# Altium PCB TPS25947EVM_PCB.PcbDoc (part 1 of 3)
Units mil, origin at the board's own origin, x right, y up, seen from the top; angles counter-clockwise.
Board outline 6500 x 3000 mil, 4 copper layers (L1-Top Layer, L2-GND1, L3-PWR/SIG, L4-Bottom Layer), stack 63.4 mil thick; 231 components, 92 nets, 448 pads, 577 vias.
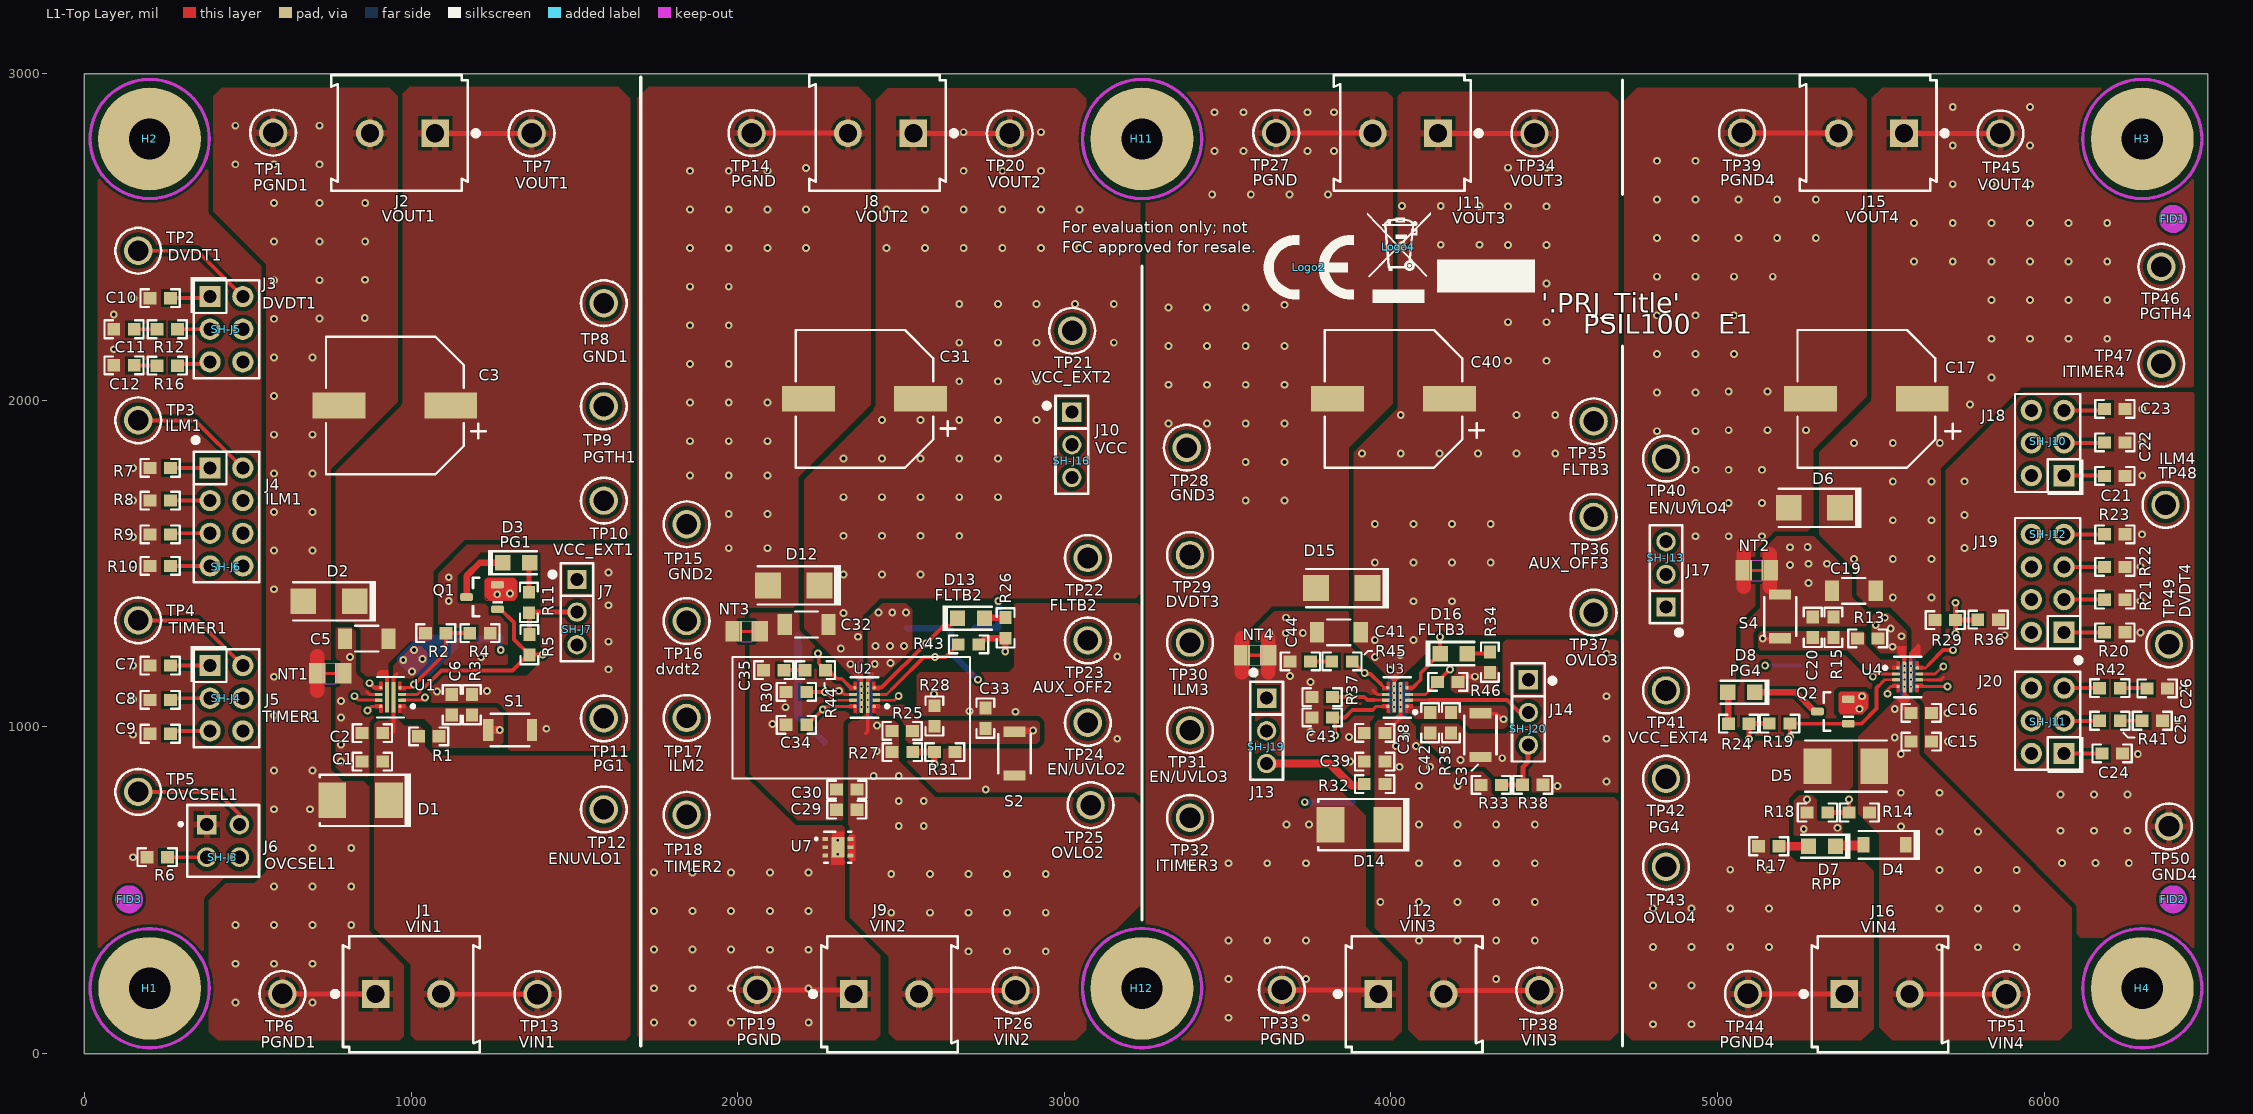
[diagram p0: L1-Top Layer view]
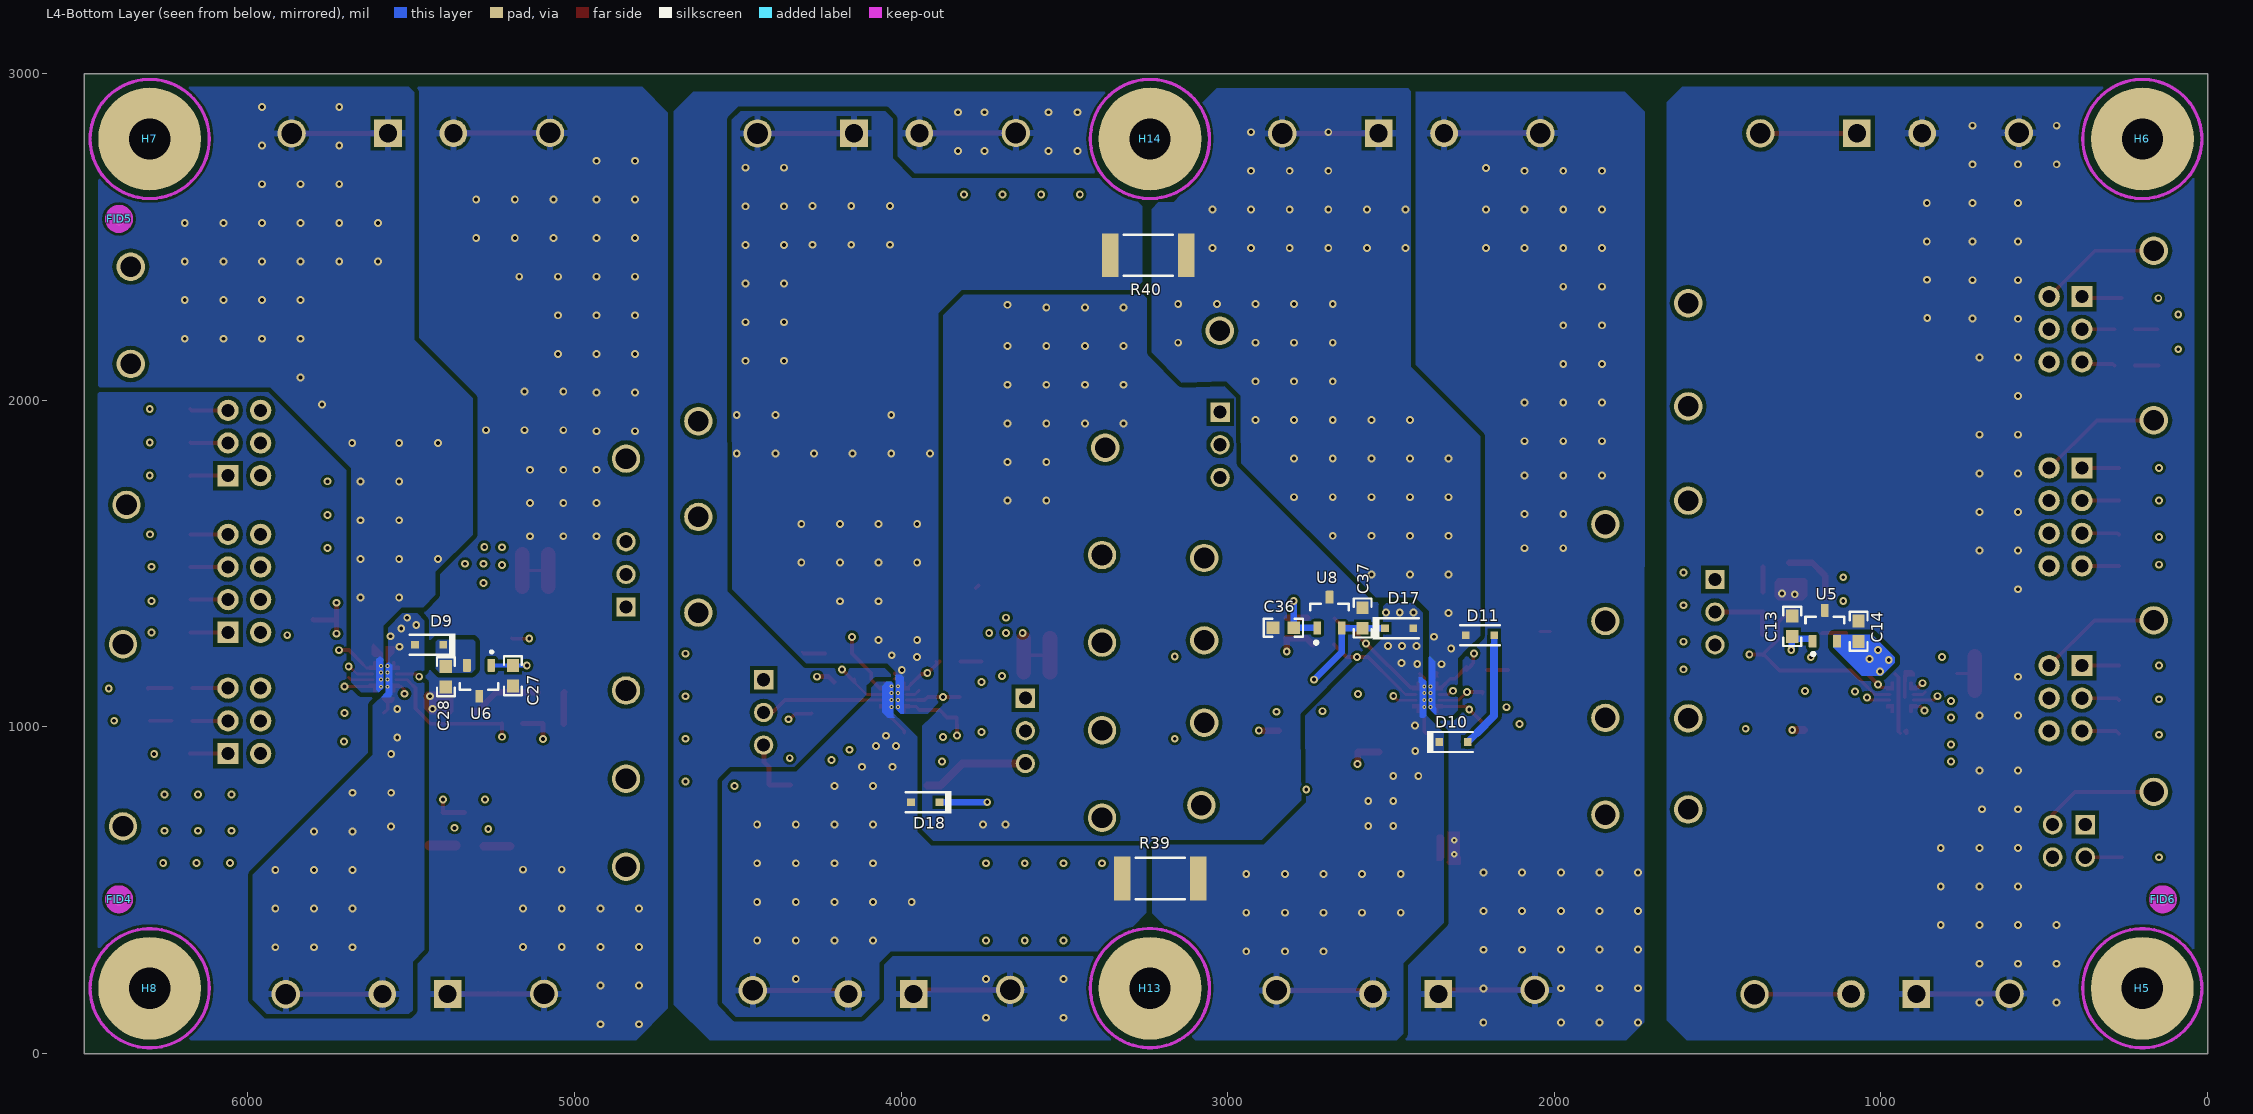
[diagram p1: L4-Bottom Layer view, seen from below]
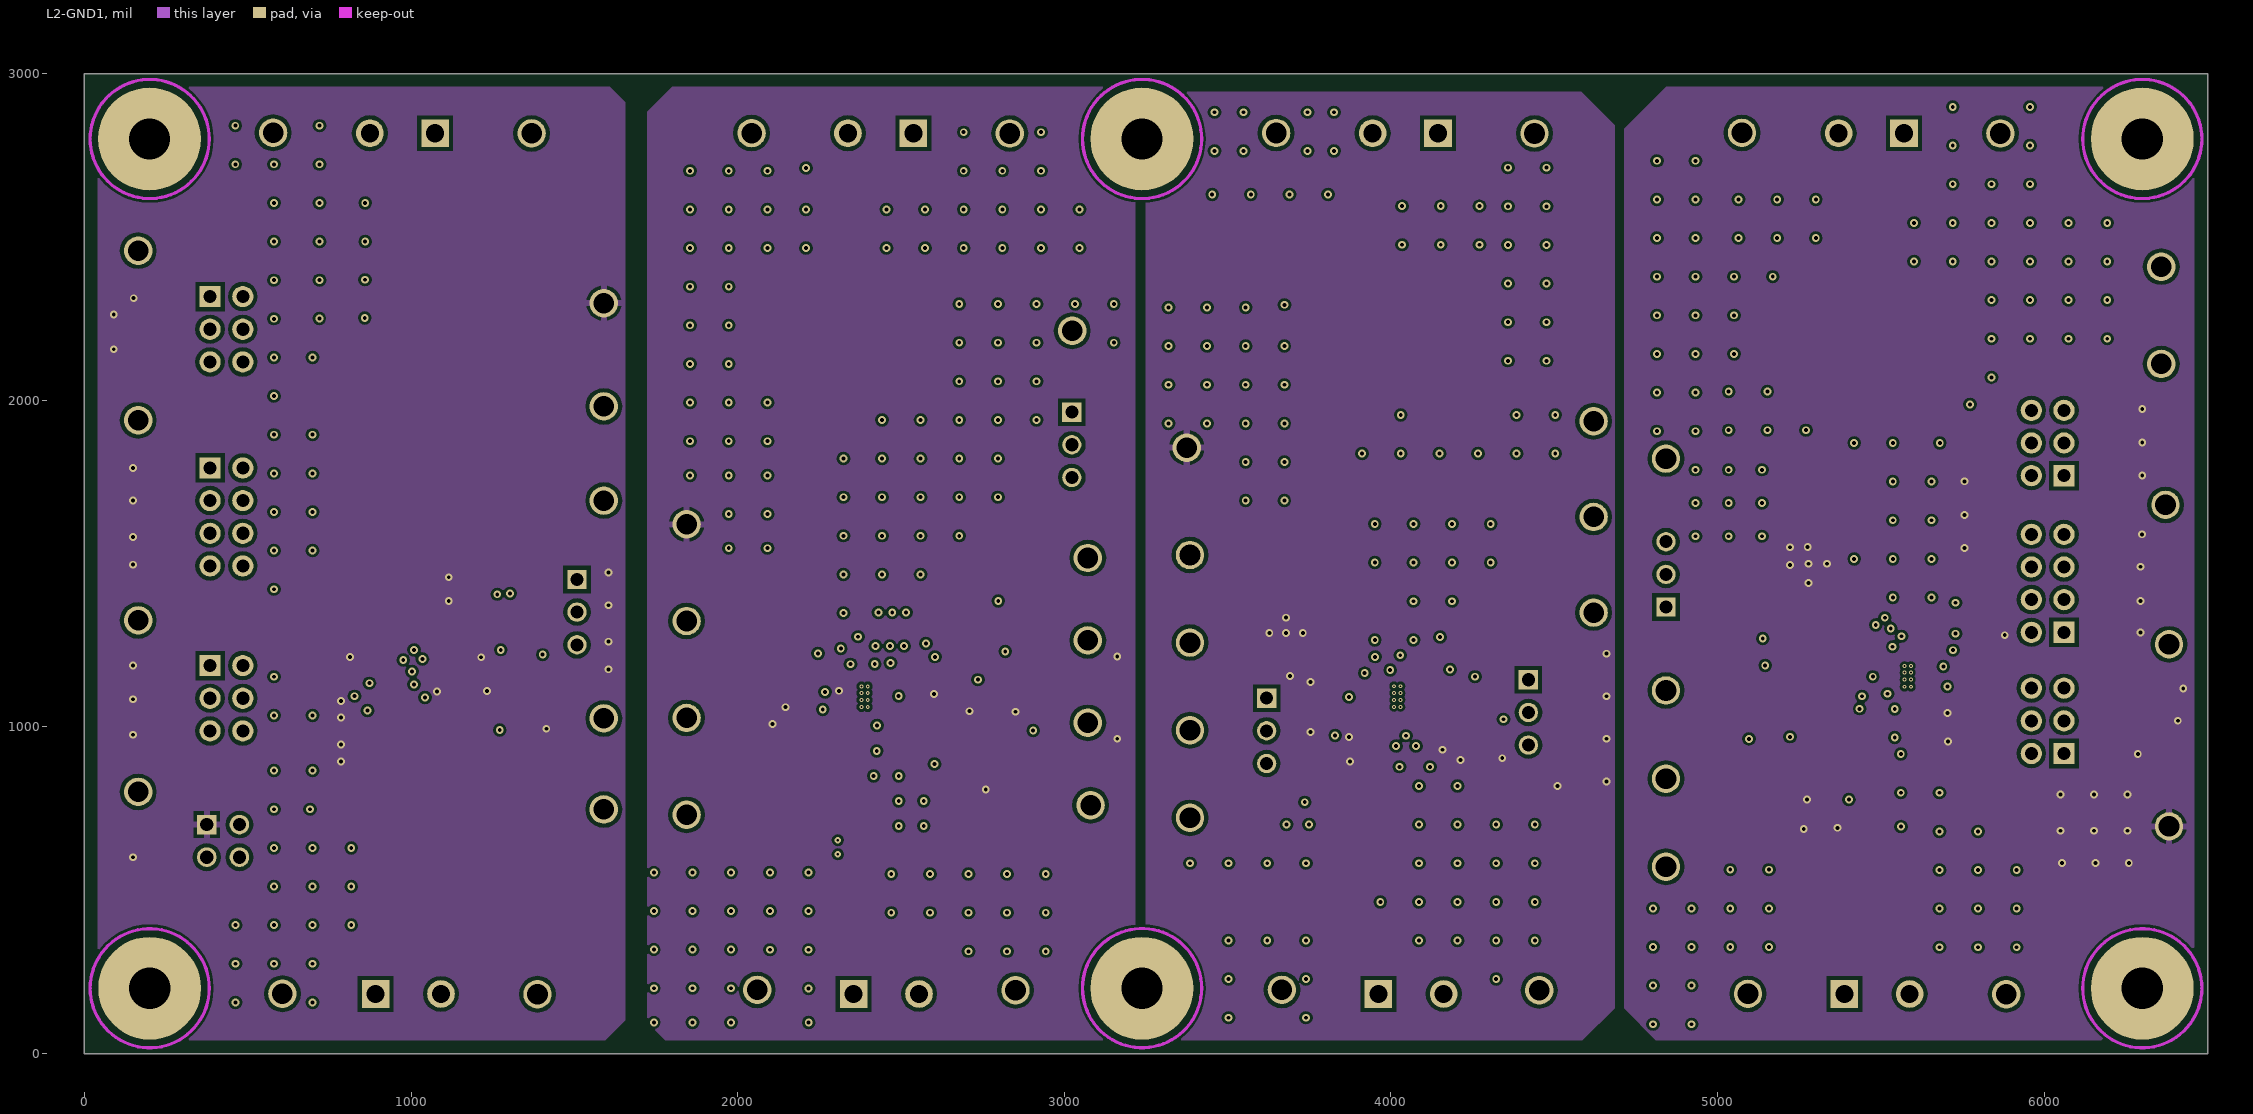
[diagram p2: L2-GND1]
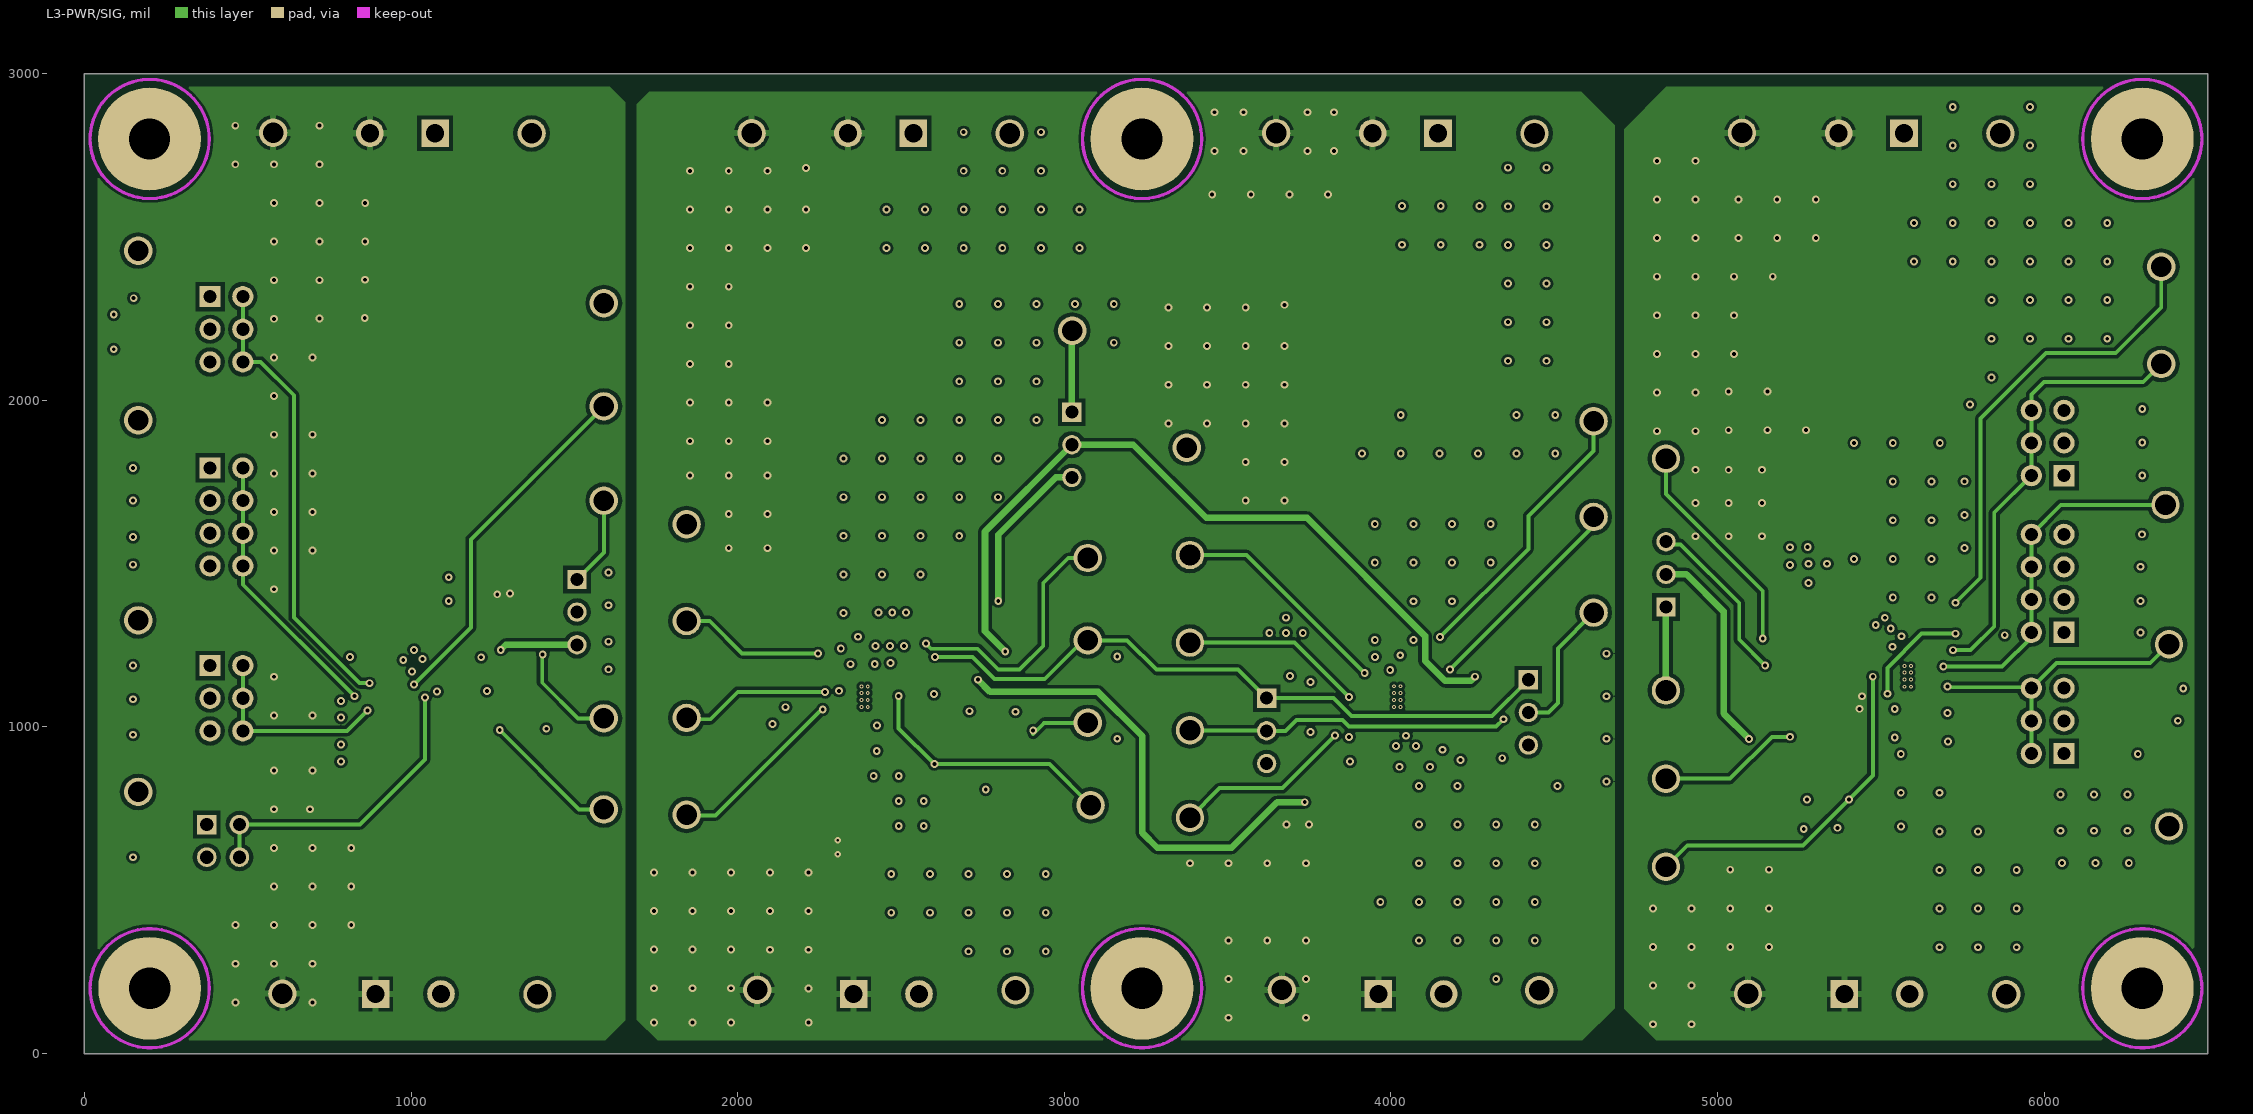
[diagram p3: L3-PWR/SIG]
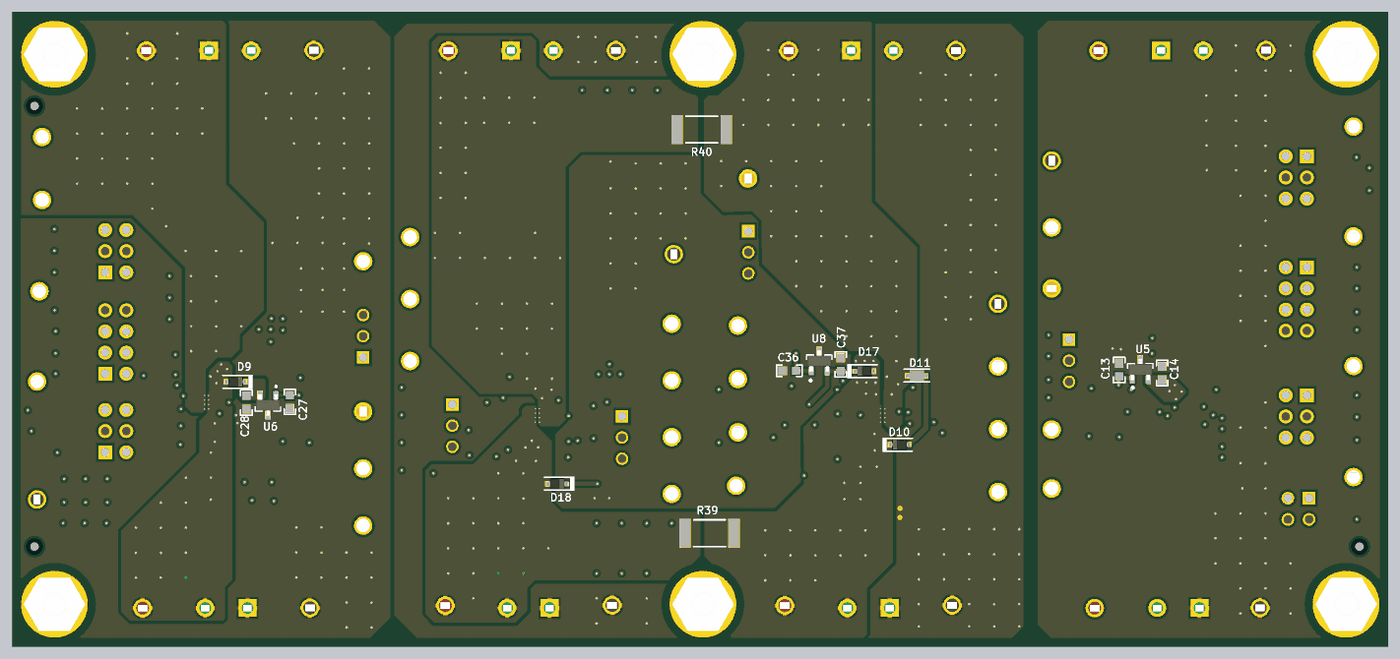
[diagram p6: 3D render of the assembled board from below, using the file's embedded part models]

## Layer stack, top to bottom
Top Solder: solder mask 0.4, Solder Resist, Dk 3.5
L1-Top Layer: signal copper 2.8
Dielectric 3: dielectric 10, FR-4 HIGH TG, Dk 4.2
L2-GND1: signal copper 1.4
Dielectric 2: dielectric 35, FR-4 HIGH TG, Dk 4.2
L3-PWR/SIG: signal copper 1.4
Dielectric1: core 10, FR-4 HIGH TG, Dk 4.2
L4-Bottom Layer: signal copper 2.8
Bottom Solder: solder mask 0.4, Solder Resist, Dk 3.5

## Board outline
0,0 6500,0 6500,3000 0,3000

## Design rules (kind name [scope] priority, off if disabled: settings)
AcuteAngle [All] p1: minimum=4.50000000000000E+0001 checktracksonly=FALSE
AssemblyTestPointUsage [All] p1: valid=2
BoardOutlineClearance [All] p1: gap=40 ignorepadtopadclearanceinfootprint=FALSE except(0: Track-OutlineEdge Text-OutlineEdge Text-CavityEdge Text-CutoutEdge Text-SplitBarrior Text-SplitContinuation)
Clearance Clearance_Fiducialmark [IsKeepOut and InComponentClass('FiducialMark') vs IsPad and InComponentClass('FiducialMark')] p1: gap=0 ignorepadtopadclearanceinfootprint=FALSE
Clearance Clearance_Keepouts [((IsTrack Or IsArc) And Not InPoly) And IsFree and IsKeepOut vs ((IsTrack Or IsArc) And Not InPoly) And IsFree and IsKeepOut] p2: gap=0 ignorepadtopadclearanceinfootprint=FALSE
Clearance "banana jack" [InPadClass('banan jack')] p3: gap=25 ignorepadtopadclearanceinfootprint=FALSE except(0: Arc-Hole Track-Hole SMDPad-Hole THPad-Hole Via-Hole Fill-Hole Poly-Hole Region-Hole Text-Hole)
Clearance [All] p4: gap=8 ignorepadtopadclearanceinfootprint=FALSE except(0: Arc-SMDPad Arc-Hole Track-Hole SMDPad-Hole THPad-Hole Via-Hole Fill-Hole Poly-Hole Region-Hole Text-Hole; 5.12: SMDPad-SMDPad; 5.8: Via-Via; 6.7: SMDPad-Via Via-Region; 6.8: Track-Via; 7.7: Track-SMDPad Track-Region; 7.87: SMDPad-Region; 10: Track-Poly THPad-THPad; 12: THPad-Poly Fill-Fill Fill-Poly; 15: Poly-Poly Poly-Region)
Clearance Clearance_Poly [InPolygon] p5: gap=15 ignorepadtopadclearanceinfootprint=FALSE except(0: Arc-SMDPad; 5.8: Via-Via; 6.7: SMDPad-Via Via-Region; 6.8: Track-Via; 10: SMDPad-Poly)
ComponentClearance ComponentClearance_MountingHoles_FiducialMarks [InComponentClass('Mounting Holes') vs InComponentClass('FiducialMark')] p1: gap=50 collisioncheckmode=3 verticalgap=10 showdistances=FALSE
ComponentClearance ComponentClearance_Shunt [InComponentClass('Header') vs InComponentClass('Shunt')] p2: gap=0 collisioncheckmode=3 verticalgap=0 showdistances=FALSE
ComponentClearance ComponentClearance_Logo [InComponentClass('Logo')] p3: gap=0 collisioncheckmode=3 verticalgap=0 showdistances=FALSE
ComponentClearance ComponentClearance_ScrewToNut [(HasFootprint('NY PMS 440 0025 PH')) vs (HasFootprint('Keystone_1902C'))] p4: gap=5 collisioncheckmode=3 verticalgap=10 showdistances=FALSE
ComponentClearance ComponentClearance_MountingHoles [InComponentClass('Mounting Holes')] p5: gap=100 collisioncheckmode=3 verticalgap=100000 showdistances=FALSE
ComponentClearance ComponentClearance_SmallPassives [HasFootprint('0201*') or HasFootprint('0402*') or HasFootprint('0508') or HasFootprint('0603*') or HasFootprint('0612') or HasFootprint('0805*') or HasFootprint('0815*') or HasFootprint('0830*') or HasFootprint('1206*') or HasFootprint('1210*') or HasFootprint('1808*') or HasFootprint('1812*') or HasFootprint('1825*') or HasFootprint('2010*') or HasFootprint('2220*') or HasFootprint('2225*') or HasFootprint('2512*') or HasFootprint('2728*') or HasFootprint('3518*') vs HasFootprint('0201*') or HasFootprint('0402*') or HasFootprint('0508') or HasFootprint('0603*') or HasFootprint('0612') or HasFootprint('0805*') or HasFootprint('0815*') or HasFootprint('0830*') or HasFootprint('1206*') or HasFootprint('1210*') or HasFootprint('1808*') or HasFootprint('1812*') or HasFootprint('1825*') or HasFootprint('2010*') or HasFootprint('2220*') or HasFootprint('2225*') or HasFootprint('2512*') or HasFootprint('2728*') or HasFootprint('3518*')] p6: gap=14.96 collisioncheckmode=3 verticalgap=10 showdistances=FALSE
ComponentClearance ComponentClearance_THtoSMT [IsThruComponent vs IsSMTComponent] p7: gap=40 collisioncheckmode=3 verticalgap=30 showdistances=FALSE
ComponentClearance ComponentClearance_THtoTH [IsThruComponent vs IsThruComponent] p8: gap=30 collisioncheckmode=3 verticalgap=30 showdistances=FALSE
ComponentClearance [All] p9: gap=10 collisioncheckmode=3 verticalgap=10 showdistances=FALSE
DiffPairsRouting [All] p1: maxlimit=100 minlimit=10 mostfreqgap=10 toplayer_minwidth=15 toplayer_maxwidth=15 toplayer_prefwidth=15 midlayer1_minwidth=15 midlayer1_maxwidth=15 midlayer1_prefwidth=15 midlayer2_minwidth=15 midlayer2_maxwidth=15 midlayer2_prefwidth=15 bottomlayer_minwidth=15 bottomlayer_maxwidth=15 bottomlayer_prefwidth=15 maxuncoupledlength=1000
FabricationTestPointUsage TestPointUsage [All] p1: valid=2 allowmultiple=FALSE
FabricationTestpoint Testpoint [All] p1: side=3 testpointundercomponent=TRUE minsize=40 maxsize=100 preferedsize=60 minholesize=0 maxholesize=40 preferedholesize=32 testpointgrid=1 allowsidetop=TRUE allowsidebottom=TRUE usegrid=TRUE gridtolerance=0.01
FanoutControl Fanout_LCC [IsLCC] p1: bgadir=Out bgaviamode=Centered fanoutstyle=Auto fanoutdirection=Alternating viagrid=1 // Fanout_LCC (Default Rule)
FanoutControl Fanout_BGA [IsBGA] p2: bgadir=Out bgaviamode=Centered fanoutstyle=Auto fanoutdirection=Alternating viagrid=1 // Fanout_BGA (Default Rule)
FanoutControl Fanout_Default [All] p4: bgadir=Out bgaviamode=Centered fanoutstyle=Auto fanoutdirection=Alternating viagrid=1 // Fanout_Default (Default Rule)
FanoutControl Fanout_Small [(CompPinCount < 5)] p5: bgadir=Out bgaviamode=Centered fanoutstyle=Auto fanoutdirection=OutThenIn viagrid=1 // Fanout_Small (Default Rule)
HoleSize [All] p1: absolutevalues=TRUE maxlimit=251 minlimit=6 maxpercent=80.000 minpercent=20.000
MinimumAnnularRing MinimumAnnularRing_ThermalPadVias [IsVia and InAnyComponent] p1: minimumring=5.91
MinimumAnnularRing [All] p2: minimumring=3
MinimumSolderMaskSliver MinimumSolderMaskSliver_Logo [InComponentClass('Logo') vs InComponentClass('Logo')] p1: minsoldermaskwidth=0.7
MinimumSolderMaskSliver [All] p2: minsoldermaskwidth=4
PlaneConnect [All] p1: planeconnectstyle=Relief reliefexpansion=10 reliefentries=4 reliefconductorwidth=10 reliefairgap=10
PolygonConnect [All] p1: thpad.connectstyle=Relief thpad.reliefconductorwidth=20 thpad.reliefentries=4 thpad.polygonreliefangle="90 Angle" thpad.airgapwidth=10 smdpad.connectstyle=Direct smdpad.reliefconductorwidth=10 smdpad.reliefentries=4 smdpad.polygonreliefangle="90 Angle" smdpad.airgapwidth=10 via.connectstyle=Direct via.reliefconductorwidth=10 via.reliefentries=4 via.polygonreliefangle="90 Angle" via.airgapwidth=10
RoutingVias ThermalPadVias [IsVia and InAnyComponent] p1: holewidth=7.87 width=19.68 viastyle="Through Hole" minholewidth=6 minwidth=12 maxholewidth=12.99 maxwidth=23.62
RoutingVias [All] p2: holewidth=12 width=24 viastyle="Through Hole" minholewidth=6 minwidth=12 maxholewidth=40 maxwidth=65
SilkToBoardRegionClearance [Not ((IsComment or IsDesignator) And (Hide <> 'False')) and not InRegion(1000,500,4000,800)] p1:
SilkToSilkClearance SilkToSilkClearance_Pb-FreeLogo [(HasFootprint('Pb-Free_Overlay_Medium') OR HasFootprint('Pb-Free_Overlay_Small')) vs (HasFootprint('Pb-Free_Overlay_Medium') OR HasFootprint('Pb-Free_Overlay_Small'))] p1: silktosilkclearance=0
SilkToSilkClearance [All] p2: silktosilkclearance=3
SilkToSolderMaskClearance SilkToComponentPadClearance [(IsPad or IsFill or IsRegion) and InAnycomponent] p1: minsilkscreentomaskgap=3 clearancetoexposedcopper=TRUE
SilkToSolderMaskClearance "Silk to Solder Mask Opening" [All] p2: minsilkscreentomaskgap=3 clearancetoexposedcopper=FALSE
SolderMaskExpansion [All] p1: expansion=1.97
Width [All] p1: maxlimit=100 minlimit=8 preferedwidth=10 checkconnectedcopper=TRUE
15 further rules are at their usual default settings.

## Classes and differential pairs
component class Shunt: SH-J3 SH-J4 SH-J5 SH-J6 SH-J7 SH-J10 SH-J11 SH-J12 SH-J13 SH-J16 SH-J19 SH-J20
component class TPS25947EVM_Page2: C29 C30 C31 C32 C33 C34 C35 C36 C37 C38 C39 C40 C41 C42 C43 C44 D10 D11 D12 D13 D14 D15 D16 D17 D18 J8 J9 J10 J11 J12 J13 J14 NT3 NT4 R25 R26 R27 R28 R30 R31 R32 R33 R34 R35 R37 R38 R39 R40 R43 R44 R45 R46 S2 S3 TP14 TP15 TP16 TP17 TP18 TP19 TP20 TP21 TP22 TP23 TP24 TP25 TP26 TP27 TP28 TP29 TP30 TP31 TP32 TP33 TP34 TP35 TP36 TP37 TP38 U2 U3 U7 U8
component class TPS25947EVM_Page1: C1 C2 C3 C5 C6 C7 C8 C9 C10 C11 C12 C13 C14 C15 C16 C17 C19 C20 C21 C22 C23 C24 C25 C26 C27 C28 D1 D2 D3 D4 D5 D6 D7 D8 D9 J1 J2 J3 J4 J5 J6 J7 J15 J16 J17 J18 J19 J20 NT1 NT2 Q1 Q2 R1 R2 R3 R4 R5 R6 R7 R8 R9 R10 R11 R12 R13 R14 R15 R16 R17 R18 R19 R20 R21 R22 R23 R24 R29 R36 R41 R42 S1 S4 TP1 TP2 TP3 TP4 TP5 TP6 TP7 TP8 TP9 TP10 TP11 TP12 TP13 TP39 TP40 TP41 TP42 TP43 TP44 TP45 TP46 TP47 TP48 TP49 TP50 TP51 U1 U4 U5 U6
component class "Mounting Holes": H1 H2 H3 H4 H11 H12
component class Header: J3 J4 J5 J6 J7 J10 J13 J14 J17 J18 J19 J20
component class AssemblyNote: ZZ1 ZZ2 ZZ3 ZZ4
component class FiducialMark: FID1 FID2 FID3 FID4 FID5 FID6
component class TPS25947EVM_Hardware: FID1 FID2 FID3 FID4 FID5 FID6 H1 H2 H3 H4 H5 H6 H7 H8 H11 H12 H13 H14 Logo2 Logo4 SH-J3 SH-J4 SH-J5 SH-J6 SH-J7 SH-J10 SH-J11 SH-J12 SH-J13 SH-J16 SH-J19 SH-J20 ZZ1 ZZ2 ZZ3 ZZ4

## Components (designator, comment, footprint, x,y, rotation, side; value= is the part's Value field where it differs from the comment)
C1 "C1608X7R1V105K080AC" 0603 881.8,894.17 r180 top value=1uF
C2 "GRM188R71H104KA93D" 0603 881.8,981.27 r180 top value=0.1uF
C3 "EEE-FC1V221P" SM_RADIAL_G 950.57,1984.01 r180 top value=220uF
C5 "CGA5L1X7R1H106K160AC" 1206_190 864.6,1270.3 r180 top value=10uF
C6 "885012006057" 0603 1124.7,1068 r90 top value=100pF
C7 "GRM188R71H221KA01D" 0603 231.93,1187.79 r180 top value=220pF
C8 "C0603C222K5RAC" 0603 231.93,1082.86 r180 top value=2200pF
C9 "C0603X223K5RACTU" 0603 231.93,979.26 r180 top value=0.022uF
C10 "C0603X332K5RACTU" 0603 231.93,2312.56 r180 top value=3300pF
C11 "GRM1885C1H103JA01D" 0603 121.3,2217.47 r180 top value=0.01uF
C12 "C0603X223K5RACTU" 0603 121.3,2107.1 r180 top value=0.022uF
C13 "06035C104KAT2A" 0603 1271.6,1307.99 r90 bottom value=0.1uF
C14 "06035C104KAT2A" 0603 1068.7,1292.89 r90 bottom value=0.1uF
C15 "C1608X7R1V105K080AC" 0603 5623,955.06 r0 top value=1uF
C16 "GRM188R71H104KA93D" 0603 5623,1043.01 r0 top value=0.1uF
C17 "EEE-FC1V221P" SM_RADIAL_G 5455.3,2004.3 r180 top value=220uF
C19 "CGA5L1X7R1H106K160AC" 1206_190 5417.1,1416.6 r180 top value=10uF
C20 "885012006057" 0603 5291.12,1304.79 r90 top value=100pF
C21 "GRM188R71H221KA01D" 0603 6215.93,1768.4 r0 top value=220pF
C22 "C0603C222K5RAC" 0603 6215.93,1871.05 r0 top value=2200pF
C23 "C0603X223K5RACTU" 0603 6215.93,1973.7 r0 top value=0.022uF
C24 "C0603X332K5RACTU" 0603 6207.83,918.7 r0 top value=3300pF
C25 "GRM1885C1H103JA01D" 0603 6330.53,1018.83 r0 top value=0.01uF
C26 "C0603X223K5RACTU" 0603 6345.53,1118 r0 top value=0.022uF
C27 "06035C104KAT2A" 0603 5188.03,1156.78 r270 bottom value=0.1uF
C28 "06035C104KAT2A" 0603 5393.49,1153.68 r270 bottom value=0.1uF
C29 "C1608X7R1V105K080AC" 0603 2333.8,746.79 r180 top value=1uF
C30 "GRM188R71H104KA93D" 0603 2334.2,808.4 r180 top value=0.1uF
C31 "EEE-FC1V221P" SM_RADIAL_G 2388.1,2004.3 r180 top value=220uF
C32 "CGA5L1X7R1H106K160AC" 1206_190 2210.8,1313.6 r180 top value=10uF
C33 "885012006057" 0603 2758.33,1026.92 r90 top value=100pF
C34 "C0603C222K5RAC" 0603 2179.8,1006.6 r180 top value=2200pF
C35 "GRM1885C1H103JA01D" 0603 2110.3,1173.87 r180 top value=0.01uF
C36 "06035C104KAT2A" 0603 2829.3,1303.8 r0 bottom value=0.1uF
C37 "06035C104KAT2A" 0603 2586.88,1333.54 r90 bottom value=0.1uF
C38 "C1608X7R1V105K080AC" 0603 3949.81,981.66 r180 top value=1uF
C39 "GRM188R71H104KA93D" 0603 3949.81,894.16 r180 top value=0.1uF
C40 "EEE-FC1V221P" SM_RADIAL_G 4007.8,2004.3 r180 top value=220uF
C41 "CGA5L1X7R1H106K160AC" 1206_190 3840.48,1289.32 r180 top value=10uF
C42 "885012006057" 0603 4119.93,1012.8 r270 top value=100pF
C43 "C0603C222K5RAC" 0603 3789.3,1029.19 r180 top value=2200pF
C44 "GRM1885C1H103JA01D" 0603 3722.51,1200.47 r180 top value=0.01uF
D1 "SMBJ16A-13-F" SMB 845.6,775.4 r180 top value=16V
D2 "B330A-13-F" SMA 748.6,1384.4 r180 top value=30V
D3 "LTST-C170KGKT" LTST-C170KGKT_Green 1322,1502.6 r180 top value=PG1
D4 "DDZ30D-7" SOD-123 5511.05,639.19 r180 top value=30V
D5 "SMBJ16CA" SMB-Bi 5392.32,879.85 r0 top value=16V
D6 "B330A-13-F" SMA 5296.03,1670.89 r180 top value=30V
D7 "LTST-C170KRKT" LED_LTST-C170_Red 5319.52,634.69 r0 top value=RPP
D8 "LTST-C170KGKT" LTST-C170KGKT_Green 5072,1106 r0 top value=PG4
D9 "BAT54WS-7-F" SOD-323 5444.48,1251.7 r0 bottom value=30V
D10 "BAT54WS-7-F" SOD-323 2308.67,954.03 r180 bottom value=30V
D11 "CDSOD323-T12SC" SOD-323-Bi 2227.5,1280.7 r180 bottom value=12V
D12 "B330A-13-F" SMA 2171.62,1433.27 r180 top value=30V
D13 "LTST-C170KRKT" LED_LTST-C170_Red 2714.26,1332.81 r180 top value=FLTb2
D14 "SMBJ16A-13-F" SMB 3902.11,700.9 r180 top value=16V
D15 "B330A-13-F" SMA 3849.49,1425.21 r180 top value=30V
D16 "LTST-C170KRKT" LED_LTST-C170_Red 4191.66,1224.52 r180 top value=FLTb3
D17 "BAT54WS-7-F" SOD-323 2474.91,1301.8 r180 bottom value=30V
D18 "BAT54WS-7-F" SOD-323 3925.8,769.66 r0 bottom value=30V
FID1 "Fiducial" Fiducial10-20 6394.02,2555.23 r0 top
FID2 "Fiducial" Fiducial10-20 6394.02,472.42 r0 top
FID3 "Fiducial" Fiducial10-20 136.81,472.42 r0 top
FID4 "Fiducial" Fiducial10-20 6394.02,472.42 r180 bottom
FID5 "Fiducial" Fiducial10-20 6394.02,2555.23 r180 bottom
FID6 "Fiducial" Fiducial10-20 136.81,472.42 r180 bottom
H1 "NY PMS 440 0025 PH" "NY PMS 440 0025 PH" 200,200 r0 top locked
H2 "NY PMS 440 0025 PH" "NY PMS 440 0025 PH" 199.5,2800 r0 top
H3 "NY PMS 440 0025 PH" "NY PMS 440 0025 PH" 6300,2800 r0 top
H4 "NY PMS 440 0025 PH" "NY PMS 440 0025 PH" 6300,200 r0 top
H5 "1902C" Keystone_1902C 200,200 r180 bottom locked
H6 "1902C" Keystone_1902C 200,2800 r180 bottom locked
H7 "1902C" Keystone_1902C 6300,2800 r180 bottom
H8 "1902C" Keystone_1902C 6300,200 r180 bottom
H11 "NY PMS 440 0025 PH" "NY PMS 440 0025 PH" 3237.4,2800 r0 top
H12 "NY PMS 440 0025 PH" "NY PMS 440 0025 PH" 3237.4,200 r0 top
H13 "1902C" Keystone_1902C 3237.4,200 r180 bottom locked
H14 "1902C" Keystone_1902C 3237.4,2800.5 r180 bottom locked
J1 "282841-2" TEC_282841-2 991.65,182.5 r0 top
J2 "282841-2" TEC_282841-2 974,2817.5 r180 top
J3 "PEC03DAAN" SULLINS_PEC03DAAN 434.95,2217.47 r270 top
J4 "PEC04DAAN" CONN_PEC04DAAN 434.95,1642.86 r270 top
J5 "PEC03DAAN" SULLINS_PEC03DAAN 434.95,1087.79 r270 top
J6 "PEC02DAAN" Sullins_PEC02DAAN 424.67,651.16 r0 top
J7 "Header_3x1_Launchpad" CONN_PEC03SAAN 1508.18,1351.48 r270 top
J8 "282841-2" TEC_282841-2 2437.5,2817.5 r180 top
J9 "282841-2" TEC_282841-2 2455.15,182.5 r0 top
J10 "Header_3x1_Launchpad" CONN_PEC03SAAN 3022.9,1863.8 r270 top
J11 "282841-2" TEC_282841-2 4043.85,2817.5 r180 top
J12 "282841-2" TEC_282841-2 4061.5,182.5 r0 top
J13 "Header_3x1_Launchpad" CONN_PEC03SAAN 3619.32,988.16 r270 top
J14 "Header_3x1_Launchpad" CONN_PEC03SAAN 4420.6,1044.4 r270 top
J15 "282841-2" TEC_282841-2 5470.35,2817.5 r180 top
J16 "282841-2" TEC_282841-2 5488,182.5 r0 top
J17 "Header_3x1_Launchpad" CONN_PEC03SAAN 4841.8,1467.1 r90 top
J18 "PEC03DAAN" SULLINS_PEC03DAAN 6010.33,1869.3 r90 top
J19 "PEC04DAAN" CONN_PEC04DAAN 6010.33,1439.7 r90 top
J20 "PEC03DAAN" SULLINS_PEC03DAAN 6010.33,1018.7 r90 top
Logo2 "CE Mark" CE_Mark_5mm 3748.89,2407.02 r0 top
Logo4 "WEEE logo" WEEE_Minimum 4022.6,2470.6 r0 top
NT1 "Net-Tie" Net-Tie_0805_HV_NoOverlay 752.8,1163.8 r0 top net-tie
NT2 "Net-Tie" Net-Tie_0805_HV_NoOverlay 5119.9,1479.2 r0 top net-tie
NT3 "Net-Tie" Net-Tie_0805_HV_NoOverlay 2028,1292.4 r0 top net-tie
NT4 "Net-Tie" Net-Tie_0805_HV_NoOverlay 3583.84,1219.32 r0 top net-tie
Q1 "2N7002" SOT-23 1217.21,1397.68 r180 top value=60V
Q2 "2N7002" SOT-23 5352.74,1047.26 r180 top value=60V
R1 "RC0603FR-071ML" 0603 1054.34,971.2 r180 top value=1.00Meg
R2 "RC0603FR-071ML" 0603 1075.55,1287.12 r180 top value=1.00Meg
R3 "CRCW0603124KFKEA" 0603 1186.4,1068 r270 top value=124k
R4 "CRCW0603124KFKEA" 0603 1211.17,1287.11 r180 top value=124k
R5 "RG1608P-103-B-T5" 0603 1362.32,1251.48 r90 top value=10.0k
R6 "RC0603FR-07392KL" 0603 222.67,601.16 r0 top value=392k
R7 "RC0603FR-076K65L" 0603 231.93,1792.86 r0 top value=6.65k
R8 "RC0603FR-071K65L" 0603 231.93,1692.86 r0 top value=1.65k
R9 "RC0603FR-07750RL" 0603 231.93,1589.24 r0 top value=750
R10 "RC0603FR-07549RL" 0603 231.93,1492.86 r0 top value=549
R11 "RC0603FR-071KL" 0603 1361.06,1381.01 r270 top value=1.00k
R12 "RC0603FR-07100RL" 0603 253.58,2217.47 r0 top value=100
R13 "RC0603FR-072ML" 0603 5459.4,1270.9 r0 top value=2.00Meg
R14 "RC0603FR-072ML" 0603 5433.52,738.02 r0 top value=2.00Meg
R15 "RC0603FR-07249KL" 0603 5354.32,1304.83 r270 top value=249k
R16 "RC0603FR-07100RL" 0603 253.58,2105.95 r0 top value=100
R17 "RC0603FR-07887RL" 0603 5156.32,634.69 r0 top value=887
R18 "RC0603FR-07158KL" 0603 5305.42,738.02 r0 top value=158k
R19 "RG1608P-103-B-T5" 0603 5189.7,1010.1 r180 top value=10.0k
R20 "RC0603FR-076K65L" 0603 6215.93,1289.7 r180 top value=6.65k
R21 "RC0603FR-071K65L" 0603 6215.93,1389.7 r180 top value=1.65k
R22 "RC0603FR-07750RL" 0603 6215.93,1489.7 r180 top value=750
R23 "RC0603FR-07549RL" 0603 6215.93,1589.7 r180 top value=549
R24 "RC0603FR-071KL" 0603 5064.4,1010 r0 top value=1.00k
R25 "RC0603FR-071ML" 0603 2503.45,987.67 r180 top value=1.00Meg
R26 "RC0603FR-071KL" 0603 2820.06,1303.21 r270 top value=1.00k
R27 "RC0603FR-071ML" 0603 2504.25,923.23 r180 top value=1.00Meg
R28 "CRCW0603124KFKEA" 0603 2602.26,1033.5 r270 top value=124k
R29 "RC0603FR-071ML" 0603 5696.8,1327.4 r180 top value=1.00Meg
R30 "RC0603FR-07549RL" 0603 2179.8,1107.2 r0 top value=549
R31 "RC0603FR-0757K6L" 0603 2633.8,923.23 r180 top value=57.6k
R32 "RC0603FR-071ML" 0603 3949.81,824.9 r0 top value=1.00Meg
R33 "RC0603FR-071ML" 0603 4307.03,822.6 r180 top value=1.00Meg
R34 "RC0603FR-071KL" 0603 4303.03,1198.2 r270 top value=1.00k
R35 "CRCW0603124KFKEA" 0603 4183.73,1012.8 r90 top value=124k
R36 "CRCW0603124KFKEA" 0603 5827.8,1328.4 r180 top value=124k
R37 "RC0603FR-07549RL" 0603 3789.3,1091.4 r0 top value=549
R38 "RC0603FR-0778K7L" 0603 4434,822.8 r180 top value=78.7k
R39 "RC6432J000CS" 2512 3206.2,535.92 r0 bottom value=0
R40 "RC6432J000CS" 2512 3243.2,2444.2 r0 bottom value=0
R41 "RC0603FR-07100RL" 0603 6200.93,1018.9 r180 top value=100
R42 "RC0603FR-07100RL" 0603 6200.93,1118.7 r180 top value=100
R43 "RC0603FR-07100KL" 0603 2706.68,1252.45 r0 top value=100k
R44 "RC0603FR-07100RL" 0603 2237.8,1173.8 r0 top value=100
R45 "RC0603FR-07100RL" 0603 3850,1200.4 r0 top value=100
R46 "RC0603FR-07100KL" 0603 4173.9,1138 r0 top value=100k
S1 "B3U-1000P" SW_B3U-1000P 1303.49,990.66 r180 top
S2 "B3U-1000P" SW_B3U-1000P 2847.38,918.11 r90 top
S3 "B3U-1000P" SW_B3U-1000P 4273.7,974.9 r90 top
S4 "B3U-1000P" SW_B3U-1000P 5191.39,1338.48 r270 top
SH-J3 "SPC02SYAN" SPC02SYAN 424.3,600.6 r0 top value=1x2
SH-J4 "SPC02SYAN" SPC02SYAN 434.97,1088.29 r0 top value=1x2
SH-J5 "SPC02SYAN" SPC02SYAN 434.44,2217.47 r0 top value=1x2
SH-J6 "SPC02SYAN" SPC02SYAN 434.9,1489.8 r0 top value=1x2
SH-J7 "SPC02SYAN" SPC02SYAN 1508.63,1299.37 r270 top value=1x2
SH-J10 "SPC02SYAN" SPC02SYAN 6012.2,1873.9 r0 top value=1x2
SH-J11 "SPC02SYAN" SPC02SYAN 6011.6,1015.3 r0 top value=1x2
SH-J12 "SPC02SYAN" SPC02SYAN 6012.1,1590.3 r0 top value=1x2
SH-J13 "SPC02SYAN" SPC02SYAN 4841.5,1518.2 r270 top value=1x2
SH-J16 "SPC02SYAN" SPC02SYAN 3022.9,1814.5 r270 top value=1x2
SH-J19 "SPC02SYAN" SPC02SYAN 3618.43,939.93 r270 top value=1x2
SH-J20 "SPC02SYAN" SPC02SYAN 4420.1,994 r270 top value=1x2
TP1 "PGND1" Keystone5011 577.8,2819 r270 top
TP2 "dVdt1" Keystone5012 164.8,2457.9 r90 top
TP3 "ILM1" Keystone5012 164.8,1938.7 r0 top
TP4 "ITIMER1" Keystone5012 164.8,1326.3 r0 top
TP5 "OVCSEL1" Keystone5012 164.8,801.16 r0 top
TP6 "PGND1" Keystone5011 606.2,183.25 r90 top
TP7 "VOUT1" Keystone5010 1369.08,2817.13 r90 top
TP8 "GND1" Keystone5011 1590.2,2297.3 r0 top
TP9 "PGTH1" Keystone5012 1590.2,1981.35 r0 top
TP10 "VCC_EXT1" Keystone5013 1590.2,1692.86 r90 top
TP11 "PG1" Keystone5012 1590.2,1026.21 r0 top
TP12 "EN/UVLO1" Keystone5012 1590.2,747.38 r90 top
TP13 "VIN1" Keystone5010 1387.1,181.75 r270 top
TP14 "PGND" Keystone5011 2042.42,2817.87 r90 top
TP15 "GND2" Keystone5011 1843.6,1620.43 r0 top
TP16 "dVdt2" Keystone5012 1843.6,1324.2 r0 top
TP17 "ILM2" Keystone5012 1843.6,1027.6 r0 top
TP18 "ITIMER2" Keystone5012 1843.6,731 r0 top
TP19 "PGND" Keystone5011 2059.7,195.15 r90 top
TP20 "VOUT2" Keystone5010 2832.95,2816.75 r90 top
TP21 "VCC_EXT2" Keystone5013 3024.1,2212.8 r0 top
TP22 "FLTb2" Keystone5012 3071.9,1517.2 r0 top
TP23 "AUX_OFF2" Keystone5012 3071.9,1264.91 r0 top
TP24 "EN/UVLO2" Keystone5012 3071.9,1012.63 r0 top
TP25 "OVLO2" Keystone5012 3080.36,760.35 r0 top
TP26 "VIN2" Keystone5010 2850.6,193.65 r90 top
TP27 "PGND" Keystone5011 3648.4,2818.25 r90 top
TP28 "GND3" Keystone5011 3374.72,1854.89 r0 top
TP29 "dVdt3" Keystone5012 3384.6,1526.27 r0 top
TP30 "ILM3" Keystone5012 3384.6,1258.1 r0 top
TP31 "EN/UVLO3" Keystone5012 3384.6,989.93 r0 top
TP32 "ITIMER3" Keystone5012 3384.6,721.77 r0 top
TP33 "PGND" Keystone5011 3666.05,195.15 r90 top
TP34 "VOUT3" Keystone5010 4439.3,2816.75 r90 top
TP35 "FLTb3" Keystone5012 4620.3,1935.8 r0 top
TP36 "AUX_OFF3" Keystone5012 4620.3,1642.9 r0 top
TP37 "OVLO3" Keystone5012 4620.3,1350 r90 top
TP38 "VIN3" Keystone5010 4453.78,193.65 r90 top
TP39 "PGND4" Keystone5011 5074.52,2818.62 r90 top
TP40 "EN/UVLO4" Keystone5012 4841.8,1821.31 r0 top
TP41 "VCC_EXT4" Keystone5013 4841.8,1111.62 r0 top
TP42 "PG4" Keystone5012 4841.8,841.6 r0 top
TP43 "OVLO4" Keystone5012 4841.8,571.91 r90 top
TP44 "PGND4" Keystone5011 5092.92,182.87 r270 top
TP45 "VOUT4" Keystone5010 5865.8,2816.75 r90 top
TP46 "PGTH4" Keystone5012 6358.1,2408.91 r90 top
TP47 "ITIMER4" Keystone5012 6358.1,2111.3 r0 top
TP48 "ILM4" Keystone5012 6371.1,1679.8 r0 top
TP49 "dVdt4" Keystone5012 6381.8,1252.9 r0 top
TP50 "GND4" Keystone5011 6381.8,695.51 r180 top
TP51 "VIN4" Keystone5010 5883.45,181.75 r90 top
U1 "TPS259472ARPWT" RPW0010A-MFG 936.77,1090.72 r180 top
U2 "TPS259470LRPWT" RPW0010A-MFG 2388.33,1090.59 r180 top
U3 "TPS259470LRPWT" RPW0010A-MFG 4019.73,1090.72 r180 top
U4 "TPS259474LRPWT" RPW0010A-MFG 5581.47,1153.24 r0 top
U5 "LM3480IM3-3.3/NOPB" DBZ0003A_N 1171.9,1309.59 r90 bottom
U6 "LM3480IM3-3.3/NOPB" DBZ0003A_N 5291.53,1141.38 r270 bottom
U7 "TVS2200DRVR" DRV0006A 2306.7,631.6 r0 top
U8 "LM3480IM3-3.3/NOPB" DBZ0003A_N 2688.2,1350 r90 bottom
ZZ1 "This Assembly Note is for PCB labels only" AssemblyNoteLabel 308,3725.4 r0 top
ZZ2 "These assemblies are ESD sensitive, ESD precautions shall be observed." AssemblyNote 309.77,3636.62 r0 top
ZZ3 "These assemblies must be clean and free from flux and all contaminants. Use of no clean flux is not acceptable." AssemblyNote 309.77,3548.06 r0 top
ZZ4 "These assemblies must comply with workmanship standards IPC-A-610 Class 2, unless otherwise specified." AssemblyNote 309.77,3459.51 r0 top

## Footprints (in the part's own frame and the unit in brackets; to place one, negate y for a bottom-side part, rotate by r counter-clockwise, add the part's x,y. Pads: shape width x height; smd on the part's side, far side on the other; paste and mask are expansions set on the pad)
0603 [mm] "0603 from SM-752 data"
  rect 1x0.95 smd: 1(-0.8,0) 2(0.8,0)
  silkscreen extent -1.52,-0.69 1.52,0.69, body extent -0.87,-0.47 0.87,0.47, height 1
1206_190 [mm] "1206_190"
  rect 1.1x1.6 smd: 1(-1.7,0) 2(1.7,0)
  silkscreen extent -0.9,-1 0.9,1, body extent -1.75,-0.95 1.75,0.95, height 1.9
2512 [mm] "Chip Resistor, Body 6.3x3.2mm, IPC Medium Density"
  rect 1.3x3.4 smd: 1(-2.95,0) 2(2.95,0)
  silkscreen extent -1.9,-1.6 1.9,1.6, body extent -3.22,-1.67 3.22,1.67, height 0.71
AssemblyNote [mil] "Assembly Note"
AssemblyNoteLabel [mil] "Assembly Note for PCB Labels"
CE_Mark_5mm [mil] "Minimum text height for CE Mark"
  silkscreen extent -138,-98 138,98
CONN_PEC03SAAN [mm] "SULLINS"
  rect 1.5x1.5 hole 1.016: 1(-2.54,0)
  round 1.5 hole 1.016: 2(0,0) 3(2.54,0)
  silkscreen extent -3.81,-2.11 3.81,1.27, body extent -3.84,-1.3 3.84,1.3, height 8.38
CONN_PEC04DAAN [mm] "SULLINS"
  rect 1.65x1.65 hole 1.016 mask+0: 1(-3.81,-1.27)
  round 1.65 hole 1.016 mask+0: 2(-3.81,1.27) 3(-1.27,-1.27) 4(-1.27,1.27) 5(1.27,-1.27) 6(1.27,1.27) 7(3.81,-1.27) 8(3.81,1.27)
  silkscreen extent -6.18,-2.6 5.08,2.54, body extent -5.08,-2.54 5.08,2.54, height 8.38
DBZ0003A_N [mm] "SOT23, 3-Leads, Body 2.9x1.3mm, Pitch 0.95mm, Lead Span 2.4mm, IPC Medium Density"
  rrect17% 1x0.6 smd: 1(-1.2,0.95) 2(-1.2,-0.95) 3(1.2,0)
  silkscreen extent 0.2,-1.5 0.7,1.5, body extent -1.26,-1.46 1.26,1.46, height 0.98
DRV0006A [mm] "SON, 6-Leads, Body 2x2mm, Pitch 0.65mm, Thermal Pad 1.6x1mm, TI Recommended"
  rrect33% 0.45x0.3 smd: 1(-0.975,0.65) 2(-0.975,0) 3(-0.975,-0.65) 4(0.975,-0.65) 5(0.975,0) 6(0.975,0.65)
  rrect14% 1x0.7 on Top Paste: 7(0,-0.45) 7(0,0.45)
  rrect10% 1x1.6 smd paste-0.5: 7(0,0)
  silkscreen extent -1.05,-1.2 1.05,1.2, body extent -1.05,-1.05 1.05,1.05, height 0.81
Fiducial10-20 [mm]
  round 1 smd mask+0.5: 1(0,0)
  L1-Top Layer keep-out circle w1.178: c0,0 r0.5
Keystone5010 [mil] "Keystone Multipurpose loops"
  round 87 hole 63: 1(0,0)
  silkscreen extent -70,-70 70,70, body extent -63,-63 63,62, height 319
Keystone5011 [mil] "Keystone Multipurpose loops"
  round 87 hole 63: 1(0,0)
  silkscreen extent -70,-70 70,70, body extent -63,-63 63,62, height 319
Keystone5012 [mil] "Keystone Multipurpose loops"
  round 87 hole 63: 1(0,0)
  silkscreen extent -70,-70 70,70, body extent -63,-63 63,62, height 319
Keystone5013 [mil] "Keystone Multipurpose loops"
  round 87 hole 63: 1(0,0)
  silkscreen extent -70,-70 70,70, body extent -63,-63 63,62, height 319
Keystone_1902C [mil] "Hex Standoff, 4-40 threaded, nylon"
  round 1 on Mech4: 0(0,0)
  body extent -145,-126 146,126, height 501
LED_LTST-C170_Red [mm] "LITE-ON"
  rect 1.2x1.2 smd: 1(-1.05,0) 2(1.05,0)
  silkscreen extent -1.6,-1 2.2,1, body extent -1.05,-0.67 1.05,0.67, height 1.1
LTST-C170KGKT_Green [mm] "LITE-ON"
  rect 1.2x1.2 smd: 1(-1.05,0) 2(1.05,0)
  silkscreen extent -1.6,-1 2.2,1, body extent -1.05,-0.67 1.05,0.67, height 1.1
Net-Tie_0805_HV_NoOverlay [mil] "0805_HV pads tied by 10mil copper trace which can be cut.  An 0805 part can be placed on pads."
  rect 50x63 smd paste-25: 1(-40,0) 2(40,0)
  L1-Top Layer lines w10: -16,0 16,0
  L1-Top Layer keep-out lines w1: -22,-30.91 -22,30.91 ; -14.96,-30.91 14.96,-30.91 ; -14.96,30.91 14.96,30.91 ; 22,-30.91 22,30.91
"NY PMS 440 0025 PH" [mm] "4-40 nylon screw and mounting hole"
  round 8 hole 3.2: 1(0,0)
  body extent -3.3,-3.3 3.3,3.3, height 2.69
RPW0010A-MFG [mm]
  round 0.27 smd paste-1000 mask+0: 1(-0.75,0.7) 10(0.75,0.7)
  rrect40% 0.6x0.25 smd paste+0 mask+0: 2(-0.9,0.225) 3(-0.9,-0.225) 8(0.9,-0.225) 9(0.9,0.225)
  round 0.255 smd paste-1000 mask+0: 4(-0.75,-0.75) 7(0.75,-0.75)
  rrect33% 0.3x2.4 smd paste-1000 mask+0: 5(-0.25,0) 6(0.25,0)
  L1-Top Layer region: -0.85,0.85 -0.85,1.15 -0.843,1.175 -0.825,1.193 -0.8,1.2 -0.8,1.2 -0.65,1.2 -0.631,1.196 -0.615,1.185 -0.604,1.169 -0.6,1.15 -0.6,1.15 -0.6,0.6 -0.604,0.581 -0.615,0.565 -0.631,0.554 -0.65,0.55 -0.65,0.55 -1.15,0.55 -1.169,0.554 -1.185,0.565 -1.196,0.581 -1.2,0.6 -1.2,0.6 -1.2,0.8 -1.193,0.825 -1.175,0.843 -1.15,0.85 -1.15,0.85
  L1-Top Layer region: -0.85,-0.85 -0.85,-1.15 -0.846,-1.169 -0.835,-1.185 -0.819,-1.196 -0.8,-1.2 -0.8,-1.2 -0.65,-1.2 -0.631,-1.196 -0.615,-1.185 -0.604,-1.169 -0.6,-1.15 -0.6,-1.15 -0.6,-0.6 -0.604,-0.581 -0.615,-0.565 -0.631,-0.554 -0.65,-0.55 -0.65,-0.55 -1.15,-0.55 -1.169,-0.554 -1.185,-0.565 -1.196,-0.581 -1.2,-0.6 -1.2,-0.6 -1.2,-0.8 -1.196,-0.819 -1.185,-0.835 -1.169,-0.846 -1.15,-0.85 -1.15,-0.85
  L1-Top Layer region: 0.85,-0.85 0.85,-1.15 0.846,-1.169 0.835,-1.185 0.819,-1.196 0.8,-1.2 0.8,-1.2 0.65,-1.2 0.631,-1.196 0.615,-1.185 0.604,-1.169 0.6,-1.15 0.6,-1.15 0.6,-0.6 0.604,-0.581 0.615,-0.565 0.631,-0.554 0.65,-0.55 0.65,-0.55 1.15,-0.55 1.169,-0.554 1.185,-0.565 1.196,-0.581 1.2,-0.6 1.2,-0.6 1.2,-0.8 1.196,-0.819 1.185,-0.835 1.169,-0.846 1.15,-0.85 1.15,-0.85
  L1-Top Layer region: 0.85,0.85 0.85,1.15 0.846,1.169 0.835,1.185 0.819,1.196 0.8,1.2 0.8,1.2 0.65,1.2 0.631,1.196 0.615,1.185 0.604,1.169 0.6,1.15 0.6,1.15 0.6,0.6 0.604,0.581 0.615,0.565 0.631,0.554 0.65,0.55 0.65,0.55 1.15,0.55 1.169,0.554 1.185,0.565 1.196,0.581 1.2,0.6 1.2,0.6 1.2,0.8 1.196,0.819 1.185,0.835 1.169,0.846 1.15,0.85 1.15,0.85
  silkscreen extent -1.88,-1.58 1.05,1.58, body extent -1.3,-1.3 1.3,1.3, height 0.25
SM_RADIAL_G [mm] "10 x 10.2mm:  Panasonic G"
  rect 4.1x2 smd: 1(-4.35,0) 2(4.35,0)
  silkscreen extent -5.35,-5.35 5.35,5.35, body extent -5.25,-5.25 5.25,5.25, height 10.5
SMA [mm] "Molded Diode, 2-Leads, Body 4.3x2.6mm, IPC Medium Density, based on OnSemi component dimensions and land pattern"
  rect 2x2 smd: 1(-2,0) 2(2,0)
  silkscreen extent -3.66,-1.57 2.79,1.57, body extent -2.6,-1.3 2.6,1.3, height 2.42
SMB [mil] "Molded Diode, 2-Leads, Body 5.4x3.6mm, IPC Medium Density, based on OnSemi component dimensions"
  rect 85x107.99 smd: 1(-87.01,0) 2(87.01,0)
  silkscreen extent -155,-82 125,82, body extent -106,-71 106,71, height 91
SMB-Bi [mil] "Molded Diode, 2-Leads, Body 5.4x3.6mm, IPC Medium Density, based on OnSemi component dimensions"
  rect 85x107.99 smd: 1(-87.01,0) 2(87.01,0)
  silkscreen extent -125,-79 125,79, body extent -104,-73 104,73, height 89
SOD-123 [mm] "On Semi recommended land pattern"
  rect 0.915x1.22 smd: 1(-1.637,0) 2(1.637,0)
  silkscreen extent -2.74,-1.17 2.03,1.17, body extent -1.93,-0.9 1.93,0.9, height 1.35
SOD-323 [mm] "NXP recommended land pattern"
  rect 0.6x0.6 smd paste-0.05: 1(-1.1,0) 2(1.1,0)
  silkscreen extent -2.06,-0.86 1.53,0.86, body extent -1.3,-0.67 1.3,0.68, height 1.1
SOD-323-Bi [mm] "SOD323, 2-Leads, Body 1.9x1.45mm, No Polarity Mark"
  rect 0.6x0.6 smd paste-0.05: 1(-1.1,0) 2(1.1,0)
  silkscreen extent -1.53,-0.77 1.53,0.77, body extent -1.27,-0.65 1.27,0.65, height 1.02
SOT-23 [mm] "SOT23, 3-Leads, Body 2.9x1.3mm, Pitch 0.95mm, Lead Span 2.5mm, IPC Medium Density"
  rrect50% 1x0.6 smd: 1(-1.2,0.95) 2(-1.2,-0.95) 3(1.2,0)
  silkscreen extent -1.62,-1.5 0.7,1.5, body extent -1.16,-1.45 1.21,1.45, height 1
SPC02SYAN [mil] "SULLINS"
  round 1 on Mech3: 0(0,0)
  body extent -98,-47 99,47, height 366
Sullins_PEC02DAAN [mil] "Sullins Connector Solutions"
  rect 60x60 hole 40: 1(-50,50)
  round 60 hole 40: 2(50,50) 3(-50,-50) 4(50,-50)
  silkscreen extent -134,-110 110,110, body extent -110,-110 110,110, height 310
SULLINS_PEC03DAAN [mm] "SULLINS"
  rect 1.65x1.65 hole 1.016 mask+0: 1(-2.54,-1.27)
  round 1.65 hole 1.016 mask+0: 2(-2.54,1.27) 3(0,-1.27) 4(0,1.27) 5(2.54,-1.27) 6(2.54,1.27)
  silkscreen extent -4.06,-2.79 3.81,2.54, body extent -3.81,-2.54 3.81,2.54, height 8.38
SW_B3U-1000P [mm] "OMRON"
  rect 0.8x1.7 smd: 1(-1.7,0) 2(1.7,0)
  silkscreen extent -1.5,-1.25 1.5,1.25, body extent -1.5,-1.25 1.5,1.25, height 1.75
TEC_282841-2 [mm] "TE Connectivity"
  rect 2.15x2.15 hole 1.4: 1(-2.54,0)
  round 2.15 hole 1.4: 2(2.54,0)
  silkscreen extent -5.9,-4.52 5.55,4.47, body extent -5.08,-4.52 5.58,4.48, height 15.2
WEEE_Minimum [mil] "WEEElie bin"
  silkscreen extent -95,-172 99,104

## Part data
C1 C15 C29 C38: library part CMP-0007052-4, "CAP, CERM, 1 uF, 35 V, +/- 10%, X7R, 0603", Cap_Case=0603, Manufacturer=TDK, Supplier Part Number 1=445-7414-1-ND, TempCo=X7R, Tolerance_%=10%, Value1=Unknown, Value2=35V, ValueDisplayed=1uF
C2 C16 C30 C39: library part CMP-0007434-4, "CAP, CERM, 0.1 uF, 50 V, +/- 10%, X7R, 0603", Cap_Case=0603, Manufacturer=MuRata, Supplier Part Number 1=490-1519-1-ND, TempCo=X7R, Tolerance_%=10%, Value1=Unknown, Value2=50V, ValueDisplayed=0.1uF
C3 C17 C31 C40: library part CMP-0010667-1, "CAP, AL, 220 uF, 35 V, +/- 20%, 0.15 ohm, SMD", Cap_Case=G, Manufacturer=Panasonic, Supplier Part Number 1=PCE4026CT-ND, Tolerance_%=20%, Value1="0.15 ohm", Value2=35V, ValueDisplayed=220uF
C5 C19 C32 C41: library part CMP-0085950-1, "CAP, CERM, 10 µF, 50 V,+/- 10%, X7R, AEC-Q200 Grade 1, 1206", Cap_Case=1206, Manufacturer=TDK, TempCo=X7R, Tolerance_%=10%, Value2=50V, ValueDisplayed=10µF
C6 C20 C33 C42: library part CMP-0006822-4, "CAP, CERM, 100 pF, 50 V, +/- 5%, C0G/NP0, 0603", Cap_Case=0603, Manufacturer="Wurth Elektronik", TempCo=C0G/NP0, Tolerance_%=5%, Value1=Unknown, Value2=50V, ValueDisplayed=100pF
C7 C21: library part CMP-0007442-1, "CAP, CERM, 220 pF, 50 V, +/- 10%, X7R, 0603", Cap_Case=0603, Manufacturer=MuRata, Supplier Part Number 1=490-1483-1-ND, TempCo=X7R, Tolerance_%=10%, Value1=Unknown, Value2=50V, ValueDisplayed=220pF
C8 C22 C34 C43: library part CMP-0006897-4, "CAP, CERM, 2200 pF, 50 V, +/- 10%, X7R, 0603", Cap_Case=0603, Manufacturer=Kemet, Supplier Part Number 1=1362428, TempCo=X7R, Tolerance_%=10%, Value1=Unknown, Value2=50V, ValueDisplayed=2200pF
C9 C12 C23 C26: library part CMP-0006984-4, "CAP, CERM, 0.022 uF, 50 V, +/- 10%, X7R, 0603", Cap_Case=0603, Manufacturer=Kemet, Supplier Part Number 1=399-5340-1-ND, TempCo=X7R, Tolerance_%=10%, Value1=Unknown, Value2=50V, ValueDisplayed=0.022uF
C10 C24: library part CMP-0006985-4, "CAP, CERM, 3300 pF, 50 V, +/- 10%, X7R, 0603", Cap_Case=0603, Manufacturer=Kemet, Supplier Part Number 1=399-5339-1-ND, TempCo=X7R, Tolerance_%=10%, Value1=Unknown, Value2=50V, ValueDisplayed=3300pF
C11 C25 C35 C44: library part CMP-0007174-4, "CAP, CERM, 0.01 uF, 50 V, +/- 5%, C0G/NP0, 0603", Cap_Case=0603, Manufacturer=MuRata, Supplier Part Number 1=490-9666-1-ND, TempCo=C0G/NP0, Tolerance_%=5%, Value1=Unknown, Value2=50V, ValueDisplayed=0.01uF
C13 C14 C27 C28 C36 C37: library part CMP-0006802-4, "CAP, CERM, 0.1 uF, 50 V, +/- 10%, X7R, 0603", Cap_Case=0603, Manufacturer=AVX, Supplier Part Number 1=478-5052-1-ND, TempCo=X7R, Tolerance_%=10%, Value1=Unknown, Value2=50V, ValueDisplayed=0.1uF
D1 D14: library part CMP-0005547-4, "Diode, TVS, Uni, 16 V, 26 Vc, SMB", Manufacturer="Diodes Inc.", Value1=600W
D2 D6 D12 D15: library part CMP-0028350-2, "Diode, Schottky, 30 V, 3 A, SMA", Manufacturer="Diodes Inc.", Value1=3A, Value2=0.5V
D3 D8: library part CMP-0002888-1, "LED, Green, SMD", Color=Green, Manufacturer=Lite-On, Supplier Part Number 1=160-1414-1-ND, Value1=W, Value2=2V
D4: library part CMP-0085162-1, "Diode, Zener, 30 V, 500 mW, SOD-123", Manufacturer="Diodes Inc.", Power_W=500mW, Value1=0.5W
D5: library part CMP-0005548-3, "Diode, TVS, Bi, 16 V, SMB", Manufacturer=Littelfuse, Value1=600W
D7 D13 D16: library part CMP-0002829-2, "LED, Red, SMD", Color=red, Manufacturer=Lite-On, Supplier Part Number 1=160-1415-1-ND, Value1=W, Value2=2V
D9 D10 D17 D18: library part CMP-0028458-1, "Diode, Schottky, 30 V, 0.2 A, SOD-323", Manufacturer="Diodes Inc.", Supplier Part Number 1=BAT54WS-FDICT-ND, Value1=0.2A, Value2=0.7V
D11: library part CMP-0006058-3, "Diode, TVS, Bi, 12 V, 29.5 Vc, SOD323, 2-Leads, Body 1.9x1.45mm, No Polarity Mark", Manufacturer=Bourns, Value1=500W
FID1 FID2 FID3 FID4 FID5 FID6: library part CMP-0077181-1, "Fiducial mark.  There is nothing to buy or mount.", Manufacturer=N/A
H1 H2 H3 H4 H11 H12: library part CMP-0003617-1, "Machine Screw, Round, #4-40 x 1/4, Nylon, Philips panhead", Manufacturer="B&F Fastener Supply", Supplier Part Number 1=H542-ND
H5 H6 H7 H8 H13 H14: library part CMP-0003610-1, "Standoff, Hex, 0.5\"L #4-40 Nylon", Manufacturer=Keystone, Supplier Part Number 1=36-1902C-ND
J1 J2 J8 J9 J11 J12 J15 J16: library part CMP-0054973-1, "Terminal Block, 2x1, 5.08mm, TH", Manufacturer="TE Connectivity", Supplier Part Number 1=A98342-ND
J3 J5 J18 J20: library part CMP-0054552-1, "Header, 100mil, 3x2, Tin, TH", Color=Black, Current_A=3A, Manufacturer="Sullins Connector Solutions", Supplier Part Number 1=S2012E-03-ND, Voltage_V=1.8kV
J4 J19: library part CMP-0054542-1, "Header, 100mil, 4x2, Tin, TH", Color=Black, Current_A=3A, Manufacturer="Sullins Connector Solutions", Supplier Part Number 1=S2012E-04-ND, Voltage_V=1.8kV
J6: library part CMP-0054558-1, "Header, 100mil, 2x2, Tin, TH", Manufacturer="Sullins Connector Solutions", Supplier Part Number 1=S2012E-02-ND
J7 J10 J13 J14 J17: library part CMP-0002338-1, "Header, 100mil, 3x1, Tin, TH", Color=Black, Current_A=3A, Manufacturer="Sullins Connector Solutions", PartNumber=PEC03SAAN, Supplier Part Number 1=S1012E-03-ND, Voltage_V=1.8kV
Logo2: library part CMP-0074844-1
Logo4: library part CMP-0074769-1
NT1 NT2 NT3 NT4: library part CMP-0078142-2, "Single point connection between nets.", Manufacturer=N/A
Q1 Q2: library part CMP-0000768-1, "MOSFET, N-CH, 60 V, 115 A, SOT-23", Manufacturer="Fairchild Semiconductor", Supplier Part Number 1=2N7002NCT-ND
R1 R2 R29: library part CMP-0022899-4, "RES, 1.00 M, 1%, 0.1 W, 0603", Manufacturer=Yageo, Power_W=100mW, Supplier Part Number 1=311-1.00MHRCT-ND, TempCo="100 ppm/C", Tolerance_%=1%, Value2=0.1W, Value_Code=1M00, ValueDisplayed=1.00M
R3 R4 R28 R35 R36: library part CMP-0022026-4, "RES, 124 k, 1%, 0.1 W, AEC-Q200 Grade 0, 0603", Manufacturer=Vishay-Dale, Power_W=100mW, Supplier Part Number 1=541-124KHCT-ND, TempCo="100 ppm/C", Tolerance_%=1%, Value2=0.1W, Value_Code=124k
R5 R19: library part CMP-0023404-3, "RES, 10.0 k, 0.1%, 0.1 W, 0603", Manufacturer="Susumu Co Ltd", Power_W=100mW, Supplier Part Number 1=RG16P10.0KBCT-ND, TempCo="25 ppm/C", Tolerance_%=0.1%, Value2=0.1W, Value_Code=10k0, ValueDisplayed=10.0k
R6: library part CMP-0023070-4, "RES, 392 k, 1%, 0.1 W, 0603", Manufacturer=Yageo, Power_W=100mW, Supplier Part Number 1=311-392KHRCT-ND, TempCo="100 ppm/C", Tolerance_%=1%, Value2=0.1W, Value_Code=392k
R7 R20: library part CMP-0023251-5, "RES, 6.65 k, 1%, 0.1 W, 0603", Manufacturer=Yageo, Power_W=100mW, Supplier Part Number 1=311-6.65KHRCT-ND, TempCo="100 ppm/C", Tolerance_%=1%, Value2=0.1W, Value_Code=6k65, ValueDisplayed=6.65k
R8 R21: library part CMP-0022885-5, "RES, 1.65 k, 1%, 0.1 W, 0603", Manufacturer=Yageo, Power_W=100mW, Supplier Part Number 1=311-1.65KHRCT-ND, TempCo="100 ppm/C", Tolerance_%=1%, Value2=0.1W, Value_Code=1k65, ValueDisplayed=1.65k
R9 R22: library part CMP-0023266-5, "RES, 750, 1%, 0.1 W, 0603", Manufacturer=Yageo, Power_W=100mW, Supplier Part Number 1=311-750HRCT-ND, TempCo="100 ppm/C", Tolerance_%=1%, Value2=0.1W, Value_Code=750R, ValueDisplayed=750
R10 R23 R30 R37: library part CMP-0023179-5, "RES, 549, 1%, 0.1 W, 0603", Manufacturer=Yageo, Power_W=100mW, Supplier Part Number 1=311-549HRCT-ND, TempCo="100 ppm/C", Tolerance_%=1%, Value2=0.1W, Value_Code=549R, ValueDisplayed=549
R11 R24 R26 R34: library part CMP-0022895-5, "RES, 1.00 k, 1%, 0.1 W, 0603", Manufacturer=Yageo, Power_W=100mW, Supplier Part Number 1=311-1.00KHRCT-ND, TempCo="100 ppm/C", Tolerance_%=1%, Value2=0.1W, Value_Code=1k00, ValueDisplayed=1.00k
R12 R16 R41 R42 R44 R45: library part CMP-0022736-4, "RES, 100, 1%, 0.1 W, 0603", Manufacturer=Yageo, Power_W=100mW, Supplier Part Number 1=311-100HRCT-ND, TempCo="100 ppm/C", Tolerance_%=1%, Value2=0.1W, Value_Code=100R, ValueDisplayed=100
R13 R14: library part CMP-0023004-4, "RES, 2.00 M, 1%, 0.1 W, 0603", Manufacturer=Yageo, Power_W=100mW, Supplier Part Number 1=311-2.00MHRCT-ND, TempCo="100 ppm/C", Tolerance_%=1%, Value2=0.1W, Value_Code=2M00, ValueDisplayed=2.00M
R15: library part CMP-0022941-4, "RES, 249 k, 1%, 0.1 W, 0603", Manufacturer=Yageo, Power_W=100mW, Supplier Part Number 1=311-249KHRCT-ND, TempCo="100 ppm/C", Tolerance_%=1%, Value2=0.1W, Value_Code=249k
R17: library part CMP-0023303-5, "RES, 887, 1%, 0.1 W, 0603", Manufacturer=Yageo, Power_W=100mW, Supplier Part Number 1=311-887HRCT-ND, TempCo="100 ppm/C", Tolerance_%=1%, Value2=0.1W, Value_Code=887R, ValueDisplayed=887
R18: library part CMP-0022812-4, "RES, 158 k, 1%, 0.1 W, 0603", Manufacturer=Yageo, Power_W=100mW, Supplier Part Number 1=311-158KHRCT-ND, TempCo="100 ppm/C", Tolerance_%=1%, Value2=0.1W, Value_Code=158k
R25 R27 R32 R33: library part CMP-0022899-2, "RES, 1.00 M, 1%, 0.1 W, 0603", Manufacturer="Yageo America", Power_W=100mW, Supplier Part Number 1=311-1.00MHRCT-ND, TempCo="200 ppm/C", Tolerance_%=1%, Value2=0.1W, Value_Code=1M00, ValueDisplayed=1.00M
R31: library part CMP-0023191-5, "RES, 57.6 k, 1%, 0.1 W, 0603", Manufacturer=Yageo, Power_W=100mW, Supplier Part Number 1=311-57.6KHRCT-ND, TempCo="100 ppm/C", Tolerance_%=1%, Value2=0.1W, Value_Code=57k6, ValueDisplayed=57.6k
R38: library part CMP-0023275-5, "RES, 78.7 k, 1%, 0.1 W, 0603", Manufacturer=Yageo, Power_W=100mW, Supplier Part Number 1=311-78.7KHRCT-ND, TempCo="100 ppm/C", Tolerance_%=1%, Value2=0.1W, Value_Code=78k7, ValueDisplayed=78.7k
